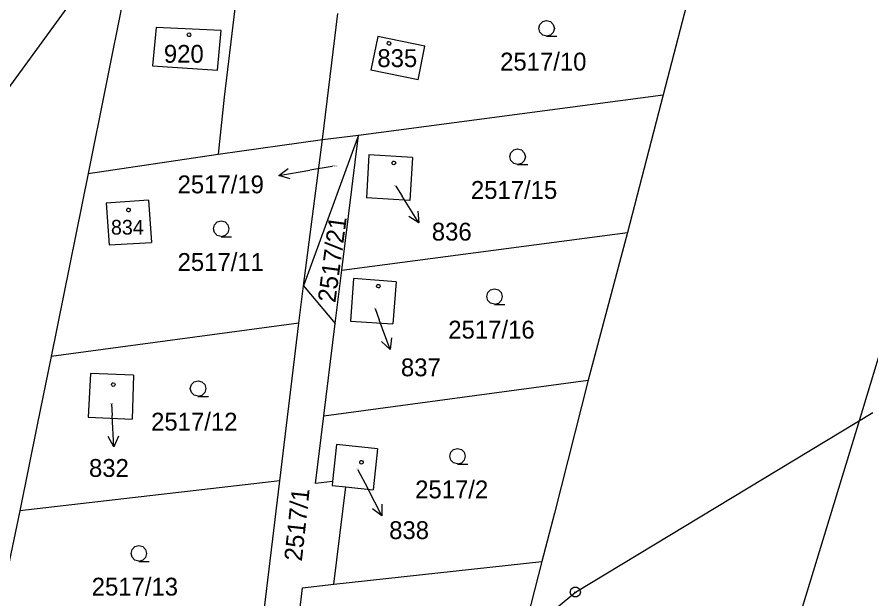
# Model space of a CAD drawing. Extents: x -760611 to -758411, y -1176479 to -1174807.
# Drawn here: x -759359.7 to -759278.5, y -1175181.7 to -1175126.3 of the extents above; entities that cross this region are included whole.
import ezdxf

# ---------------------------------------------------------------- set-up
doc = ezdxf.new("R2010")
doc.units = 0
for name, color, linetype in [('1', 7, 'Continuous'), ('11', 7, 'Continuous'), ('12', 7, 'Continuous'), ('2', 7, 'Continuous'), ('3', 7, 'Continuous'), ('5', 7, 'Continuous'), ('7', 7, 'Continuous'), ('8', 7, 'Continuous')]:
    doc.layers.add(name, color=color, linetype=linetype)

msp = doc.modelspace()

# ---------------------------------------------------------------- linework, layer by layer
at = {"layer": '1'}
for p, q in [((-759342.79, -1175090.74), (-759352.98, -1175141.22)), ((-759338.48, -1175121.14), (-759340.03, -1175133.95)), ((-759295.17, -1175121.91), (-759298.25, -1175133.73)), ((-759330.67, -1175137.98), (-759329.21, -1175126)), ((-759346.51, -1175127.31), (-759346.84, -1175130.97)), ((-759340.32, -1175127.6), (-759346.51, -1175127.31)), ((-759340.65, -1175131.39), (-759340.32, -1175127.6)), ((-759325.4, -1175128.17), (-759326.06, -1175131.37)), ((-759320.92, -1175129.09), (-759325.4, -1175128.17)), ((-759321.57, -1175132.3), (-759320.92, -1175129.09)), ((-759346.84, -1175130.97), (-759340.65, -1175131.39)), ((-759321.57, -1175132.3), (-759326.06, -1175131.37)), ((-759327.24, -1175137.56), (-759298.25, -1175133.73)), ((-759298.25, -1175133.73), (-759301.65, -1175146.83)), ((-759340.03, -1175133.95), (-759340.6, -1175139.37)), ((-759340.6, -1175139.37), (-759330.67, -1175137.98)), ((-759327.24, -1175137.56), (-759332.46, -1175151.92)), ((-759332.46, -1175151.92), (-759330.67, -1175137.98)), ((-759330.67, -1175137.98), (-759327.24, -1175137.56)), ((-759328.83, -1175150.44), (-759327.24, -1175137.56)), ((-759352.98, -1175141.22), (-759340.6, -1175139.37)), ((-759326.25, -1175139.45), (-759326.49, -1175143.55)), ((-759322.09, -1175139.69), (-759326.25, -1175139.45)), ((-759322.09, -1175139.69), (-759322.36, -1175143.79)), ((-759352.98, -1175141.22), (-759356.49, -1175158.64)), ((-759322.36, -1175143.79), (-759326.49, -1175143.55)), ((-759347.22, -1175143.75), (-759351.27, -1175144.06)), ((-759351.27, -1175144.06), (-759350.97, -1175148.02)), ((-759347.22, -1175143.75), (-759346.93, -1175147.79)), ((-759328.83, -1175150.44), (-759301.65, -1175146.83)), ((-759301.65, -1175146.83), (-759305.37, -1175160.9)), ((-759350.97, -1175148.02), (-759346.93, -1175147.79)), ((-759329.46, -1175155.51), (-759328.83, -1175150.44)), ((-759327.71, -1175151.23), (-759328, -1175155.27)), ((-759323.67, -1175151.53), (-759327.71, -1175151.23)), ((-759323.67, -1175151.53), (-759323.97, -1175155.54)), ((-759332.92, -1175155.46), (-759332.46, -1175151.92)), ((-759332.46, -1175151.92), (-759329.46, -1175155.51)), ((-759332.92, -1175155.46), (-759356.49, -1175158.64)), ((-759334.73, -1175170.49), (-759332.92, -1175155.46)), ((-759330.55, -1175164.31), (-759329.46, -1175155.51)), ((-759328, -1175155.27), (-759323.97, -1175155.54)), ((-759356.49, -1175158.64), (-759357.81, -1175165.16)), ((-759352.76, -1175160.25), (-759352.96, -1175164.42)), ((-759348.67, -1175160.43), (-759352.76, -1175160.25)), ((-759348.67, -1175160.43), (-759348.78, -1175164.6)), ((-759330.55, -1175164.31), (-759305.37, -1175160.9)), ((-759305.37, -1175160.9), (-759308.59, -1175173.55)), ((-759306.6, -1175181.08), (-759278.28, -1175163.97)), ((-759352.96, -1175164.42), (-759348.78, -1175164.6)), ((-759331.34, -1175170.75), (-759330.55, -1175164.31)), ((-759357.81, -1175165.16), (-759359.46, -1175173.34)), ((-759329.34, -1175167.02), (-759329.7, -1175170.56)), ((-759325.42, -1175167.44), (-759329.34, -1175167.02)), ((-759325.42, -1175167.44), (-759325.84, -1175171.35)), ((-759334.73, -1175170.49), (-759359.46, -1175173.34)), ((-759336.51, -1175185.32), (-759334.73, -1175170.49)), ((-759329.7, -1175170.56), (-759331.34, -1175170.75)), ((-759329.7, -1175170.56), (-759329.74, -1175170.92)), ((-759329.74, -1175170.92), (-759328.45, -1175171.06)), ((-759329.59, -1175180.33), (-759328.45, -1175171.06)), ((-759328.45, -1175171.06), (-759325.84, -1175171.35)), ((-759359.46, -1175173.34), (-759362.4, -1175187.18)), ((-759308.59, -1175173.55), (-759309.78, -1175178.15)), ((-759329.59, -1175180.33), (-759309.78, -1175178.15)), ((-759309.78, -1175178.15), (-759311.62, -1175185.22)), ((-759334.64, -1175197.47), (-759332.57, -1175180.66)), ((-759332.57, -1175180.66), (-759329.59, -1175180.33)), ((-759311.62, -1175185.22), (-759306.6, -1175181.08))]:
    msp.add_line(p, q, dxfattribs=at)
at = {"layer": '11'}
for points in [[(-759277.4, -1175081.41), (-759285.99, -1175083.38), (-759286.68, -1175083.54), (-759295.93, -1175086.38), (-759305.65, -1175089.38), (-759307.82, -1175090.04), (-759312.08, -1175091.35), (-759315.12, -1175092.29), (-759315.34, -1175092.43), (-759325.61, -1175098.82), (-759334.67, -1175104.46), (-759335.87, -1175105.55), (-759347.99, -1175116.51), (-759349.56, -1175117.93), (-759372.57, -1175149.55), (-759378.11, -1175156.29), (-759381.94, -1175161.35), (-759383.07, -1175162.46), (-759387.05, -1175166.4), (-759387.91, -1175169.78), (-759407.11, -1175194.59)], [(-759302.17, -1175262.03), (-759302.03, -1175261.55), (-759299.47, -1175252.11), (-759298.73, -1175249.35), (-759297.4, -1175234.13), (-759293.92, -1175210.45), (-759292.63, -1175205.38), (-759291.77, -1175202), (-759288.78, -1175195.24), (-759288.34, -1175191.86), (-759285.77, -1175185.1), (-759279.57, -1175164.75), (-759276.09, -1175153.33), (-759274.19, -1175147.08), (-759269.92, -1175137.79), (-759267.35, -1175132.72), (-759260.94, -1175117.52), (-759255.81, -1175107.39), (-759254.95, -1175102.32), (-759253.24, -1175098.94), (-759251.12, -1175100.22), (-759246.85, -1175092.2)]]:
    msp.add_lwpolyline(points, dxfattribs=at)
at = {"layer": '12'}
for p, q in [((-759346.51, -1175127.31), (-759346.84, -1175130.97)), ((-759340.32, -1175127.6), (-759346.51, -1175127.31)), ((-759340.65, -1175131.39), (-759340.32, -1175127.6)), ((-759325.4, -1175128.17), (-759326.06, -1175131.37)), ((-759320.92, -1175129.09), (-759325.4, -1175128.17)), ((-759321.57, -1175132.3), (-759320.92, -1175129.09)), ((-759346.84, -1175130.97), (-759340.65, -1175131.39)), ((-759321.57, -1175132.3), (-759326.06, -1175131.37)), ((-759326.25, -1175139.45), (-759326.49, -1175143.55)), ((-759322.09, -1175139.69), (-759326.25, -1175139.45)), ((-759322.09, -1175139.69), (-759322.36, -1175143.79)), ((-759322.36, -1175143.79), (-759326.49, -1175143.55)), ((-759347.22, -1175143.75), (-759351.27, -1175144.06)), ((-759351.27, -1175144.06), (-759350.97, -1175148.02)), ((-759347.22, -1175143.75), (-759346.93, -1175147.79)), ((-759350.97, -1175148.02), (-759346.93, -1175147.79)), ((-759327.71, -1175151.23), (-759328, -1175155.27)), ((-759323.67, -1175151.53), (-759327.71, -1175151.23)), ((-759323.67, -1175151.53), (-759323.97, -1175155.54)), ((-759328, -1175155.27), (-759323.97, -1175155.54)), ((-759352.76, -1175160.25), (-759352.96, -1175164.42)), ((-759348.67, -1175160.43), (-759352.76, -1175160.25)), ((-759348.67, -1175160.43), (-759348.78, -1175164.6)), ((-759352.96, -1175164.42), (-759348.78, -1175164.6)), ((-759329.34, -1175167.02), (-759329.7, -1175170.56)), ((-759325.42, -1175167.44), (-759329.34, -1175167.02)), ((-759325.42, -1175167.44), (-759325.84, -1175171.35)), ((-759329.7, -1175170.56), (-759329.74, -1175170.92)), ((-759329.74, -1175170.92), (-759328.45, -1175171.06)), ((-759328.45, -1175171.06), (-759325.84, -1175171.35))]:
    msp.add_line(p, q, dxfattribs=at)
at = {"layer": '3'}
for points in [[(-759309.33, -1175128.14), (-759309.71, -1175128.04), (-759309.98, -1175127.77), (-759310.08, -1175127.4), (-759309.98, -1175127.03), (-759309.71, -1175126.76), (-759309.34, -1175126.66), (-759308.97, -1175126.76), (-759308.7, -1175127.03), (-759308.6, -1175127.41), (-759308.7, -1175127.79), (-759308.97, -1175128.06), (-759309.35, -1175128.16), (-759308.35, -1175128.16)], [(-759312.09, -1175140.36), (-759312.47, -1175140.26), (-759312.74, -1175139.99), (-759312.84, -1175139.62), (-759312.74, -1175139.25), (-759312.47, -1175138.98), (-759312.1, -1175138.88), (-759311.73, -1175138.98), (-759311.46, -1175139.25), (-759311.36, -1175139.63), (-759311.46, -1175140.01), (-759311.73, -1175140.28), (-759312.11, -1175140.38), (-759311.11, -1175140.38)], [(-759340.3, -1175147.22), (-759340.68, -1175147.12), (-759340.95, -1175146.85), (-759341.05, -1175146.48), (-759340.95, -1175146.11), (-759340.68, -1175145.84), (-759340.31, -1175145.74), (-759339.94, -1175145.84), (-759339.67, -1175146.11), (-759339.57, -1175146.49), (-759339.67, -1175146.87), (-759339.94, -1175147.14), (-759340.32, -1175147.24), (-759339.32, -1175147.24)], [(-759314.29, -1175153.67), (-759314.67, -1175153.57), (-759314.94, -1175153.3), (-759315.04, -1175152.93), (-759314.94, -1175152.56), (-759314.67, -1175152.29), (-759314.3, -1175152.19), (-759313.93, -1175152.29), (-759313.66, -1175152.56), (-759313.56, -1175152.94), (-759313.66, -1175153.32), (-759313.93, -1175153.59), (-759314.31, -1175153.69), (-759313.31, -1175153.69)], [(-759342.5, -1175162.43), (-759342.88, -1175162.33), (-759343.15, -1175162.06), (-759343.25, -1175161.69), (-759343.15, -1175161.32), (-759342.88, -1175161.05), (-759342.51, -1175160.95), (-759342.14, -1175161.05), (-759341.87, -1175161.32), (-759341.77, -1175161.7), (-759341.87, -1175162.08), (-759342.14, -1175162.35), (-759342.52, -1175162.45), (-759341.52, -1175162.45)], [(-759317.81, -1175168.88), (-759318.19, -1175168.78), (-759318.46, -1175168.51), (-759318.56, -1175168.14), (-759318.46, -1175167.77), (-759318.19, -1175167.5), (-759317.82, -1175167.4), (-759317.45, -1175167.5), (-759317.18, -1175167.77), (-759317.08, -1175168.15), (-759317.18, -1175168.53), (-759317.45, -1175168.8), (-759317.83, -1175168.9), (-759316.83, -1175168.9)], [(-759348.14, -1175178.13), (-759348.52, -1175178.03), (-759348.79, -1175177.76), (-759348.89, -1175177.39), (-759348.79, -1175177.02), (-759348.52, -1175176.75), (-759348.15, -1175176.65), (-759347.78, -1175176.75), (-759347.51, -1175177.02), (-759347.41, -1175177.4), (-759347.51, -1175177.78), (-759347.78, -1175178.05), (-759348.16, -1175178.15), (-759347.16, -1175178.15)]]:
    msp.add_lwpolyline(points, dxfattribs=at)
at = {"layer": '5'}
for points in [[(-759343.38, -1175127.84), (-759343.28, -1175127.86), (-759343.23, -1175127.95), (-759343.21, -1175128.01), (-759343.23, -1175128.1), (-759343.31, -1175128.17), (-759343.38, -1175128.18), (-759343.47, -1175128.15), (-759343.53, -1175128.09), (-759343.55, -1175128.01), (-759343.53, -1175127.92), (-759343.45, -1175127.85)], [(-759324.34, -1175128.66), (-759324.24, -1175128.68), (-759324.19, -1175128.77), (-759324.17, -1175128.83), (-759324.19, -1175128.92), (-759324.27, -1175128.99), (-759324.34, -1175129), (-759324.43, -1175128.97), (-759324.49, -1175128.91), (-759324.51, -1175128.83), (-759324.49, -1175128.74), (-759324.41, -1175128.67)], [(-759323.88, -1175140.05), (-759323.78, -1175140.07), (-759323.73, -1175140.16), (-759323.71, -1175140.22), (-759323.73, -1175140.31), (-759323.81, -1175140.38), (-759323.88, -1175140.39), (-759323.97, -1175140.36), (-759324.03, -1175140.3), (-759324.05, -1175140.22), (-759324.03, -1175140.13), (-759323.95, -1175140.06)], [(-759349.13, -1175144.53), (-759349.03, -1175144.55), (-759348.98, -1175144.64), (-759348.96, -1175144.7), (-759348.98, -1175144.79), (-759349.06, -1175144.86), (-759349.13, -1175144.87), (-759349.22, -1175144.84), (-759349.28, -1175144.78), (-759349.3, -1175144.7), (-759349.28, -1175144.61), (-759349.2, -1175144.54)], [(-759325.35, -1175151.78), (-759325.25, -1175151.8), (-759325.2, -1175151.89), (-759325.18, -1175151.95), (-759325.2, -1175152.04), (-759325.28, -1175152.11), (-759325.35, -1175152.12), (-759325.44, -1175152.09), (-759325.5, -1175152.03), (-759325.52, -1175151.95), (-759325.5, -1175151.86), (-759325.42, -1175151.79)], [(-759350.58, -1175161.15), (-759350.48, -1175161.17), (-759350.43, -1175161.26), (-759350.41, -1175161.32), (-759350.43, -1175161.41), (-759350.51, -1175161.48), (-759350.58, -1175161.49), (-759350.67, -1175161.46), (-759350.73, -1175161.4), (-759350.75, -1175161.32), (-759350.73, -1175161.23), (-759350.65, -1175161.16)], [(-759326.96, -1175168.55), (-759326.86, -1175168.57), (-759326.81, -1175168.66), (-759326.79, -1175168.72), (-759326.81, -1175168.81), (-759326.89, -1175168.88), (-759326.96, -1175168.89), (-759327.05, -1175168.86), (-759327.11, -1175168.8), (-759327.13, -1175168.72), (-759327.11, -1175168.63), (-759327.03, -1175168.56)]]:
    msp.add_lwpolyline(points, close=True, dxfattribs=at)
at = {"layer": '7'}
for p, q in [((-759334.829, -1175141.406), (-759331.87, -1175140.91)), ((-759329.76, -1175140.56), (-759331.87, -1175140.91)), ((-759323.68, -1175142.43), (-759323.09, -1175143.37)), ((-759321.495, -1175145.911), (-759323.09, -1175143.37)), ((-759325.65, -1175154.09), (-759325.26, -1175155.16)), ((-759324.23, -1175157.978), (-759325.26, -1175155.16)), ((-759350.75, -1175163.16), (-759350.69, -1175164.25)), ((-759350.53, -1175167.246), (-759350.69, -1175164.25)), ((-759327.3, -1175169.43), (-759326.4, -1175171.16)), ((-759325.014, -1175173.82), (-759326.4, -1175171.16))]:
    msp.add_line(p, q, dxfattribs=at)
for points in [[(-759333.76, -1175141.734), (-759334.829, -1175141.406), (-759333.925, -1175140.748)], [(-759321.603, -1175144.798), (-759321.495, -1175145.911), (-759322.45, -1175145.33)], [(-759324.104, -1175156.867), (-759324.23, -1175157.978), (-759325.043, -1175157.21)], [(-759350.084, -1175166.22), (-759350.53, -1175167.246), (-759351.083, -1175166.274)], [(-759325.032, -1175172.703), (-759325.014, -1175173.82), (-759325.919, -1175173.165)]]:
    msp.add_lwpolyline(points, dxfattribs=at)
at = {"layer": '8'}
msp.add_line((-759306.72, -1175181.08), (-759306.48, -1175181.08), dxfattribs=at)
msp.add_lwpolyline([(-759306.45, -1175180.6), (-759306.2, -1175180.78), (-759306.1, -1175181.07), (-759306.2, -1175181.36), (-759306.45, -1175181.54), (-759306.76, -1175181.54), (-759307.01, -1175181.36), (-759307.11, -1175181.07), (-759307.01, -1175180.78), (-759306.76, -1175180.6)], close=True, dxfattribs=at)

# ---------------------------------------------------------------- texts
at = {"layer": '2'}
for s, height, p in [('920', 1.7, (-759345.765, -1175130.68)), ('835', 1.7, (-759325.445, -1175131.09)), ('2517/10', 1.7, (-759313.763, -1175131.42)), ('2517/19', 0.1, (-759329.746, -1175140.56)), ('2517/15', 1.7, (-759316.543, -1175143.64)), ('836', 0.1, (-759323.802, -1175142.43)), ('834', 1.4, (-759350.803, -1175147.04)), ('2517/11', 1.7, (-759344.458, -1175150.5)), ('837', 0.1, (-759325.769, -1175154.09)), ('2517/16', 1.7, (-759318.696, -1175156.94)), ('832', 0.1, (-759350.876, -1175163.16)), ('2517/12', 1.7, (-759346.98, -1175165.7)), ('838', 0.1, (-759327.423, -1175169.43)), ('2517/2', 1.7, (-759321.848, -1175172.15)), ('2517/13', 1.7, (-759352.633, -1175181.41))]:
    msp.add_text(s, height=height, dxfattribs=at).set_placement(p)
for s, rotation, p in [('2517/21', 82.33404, (-759329.448, -1175153.575)), ('2517/1', 83.82373, (-759332.634, -1175178.194))]:
    msp.add_text(s, height=1.7, rotation=rotation, dxfattribs=at).set_placement(p)
at = {"layer": '7'}
for s, p in [('2517/19', (-759344.46, -1175143.11)), ('836', (-759320.263, -1175147.61)), ('837', (-759323.203, -1175160.53)), ('832', (-759352.891, -1175170.11)), ('838', (-759324.323, -1175176.03))]:
    msp.add_text(s, height=1.7, dxfattribs=at).set_placement(p)

doc.saveas('drawing.dxf')
